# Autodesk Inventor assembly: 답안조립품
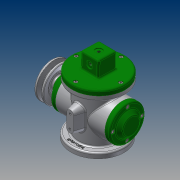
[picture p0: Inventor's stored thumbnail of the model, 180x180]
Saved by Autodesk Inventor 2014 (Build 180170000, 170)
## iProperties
Created: 2018-02
Part Number: 답안조립품
Document SubType Name: Assembly
Designer: user
Author: user
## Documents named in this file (18)
- C:\Users\user\Desktop\480207V1015\답안조립품.iam
- C:\Users\user\Desktop\480207V1015\본체.ipt
- C:\Users\user\Desktop\480207V1015\E-링.ipt
- C:\Users\user\Desktop\480207V1015\V-벨트풀리.ipt
- C:\Users\user\Desktop\480207V1015\덮개.ipt
- C:\Users\user\Desktop\480207V1015\뒤커버.ipt
- C:\Users\user\Desktop\480207V1015\링크.ipt
- C:\Users\user\Desktop\480207V1015\베어링 17 x 40 x 12.ipt
- C:\Users\user\Desktop\480207V1015\볼트 M4 x 8.ipt
- C:\Users\user\Desktop\480207V1015\볼트 M4 x 10.ipt
- C:\Users\user\Desktop\480207V1015\슬라이더.ipt
- C:\Users\user\Desktop\480207V1015\앞커버.ipt
- C:\Users\user\Desktop\480207V1015\오일 실 17 30 8.ipt
- C:\Users\user\Desktop\480207V1015\와셔 4x16.ipt
- C:\Users\user\Desktop\480207V1015\클레비스 핀 6 x 22.ipt
- 클레비스 핀 6 x 22.ipt
- C:\Users\user\Desktop\480207V1015\키 4 x 4 x 12.ipt
- C:\Users\user\Desktop\480207V1015\편심축.ipt
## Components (2 placed, 2 different names)
1. E-링:1
2. V-벨트풀리:1 — 각도:2
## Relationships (1: Angle 1)
- 각도:2 [Angle]: V-벨트풀리:1
